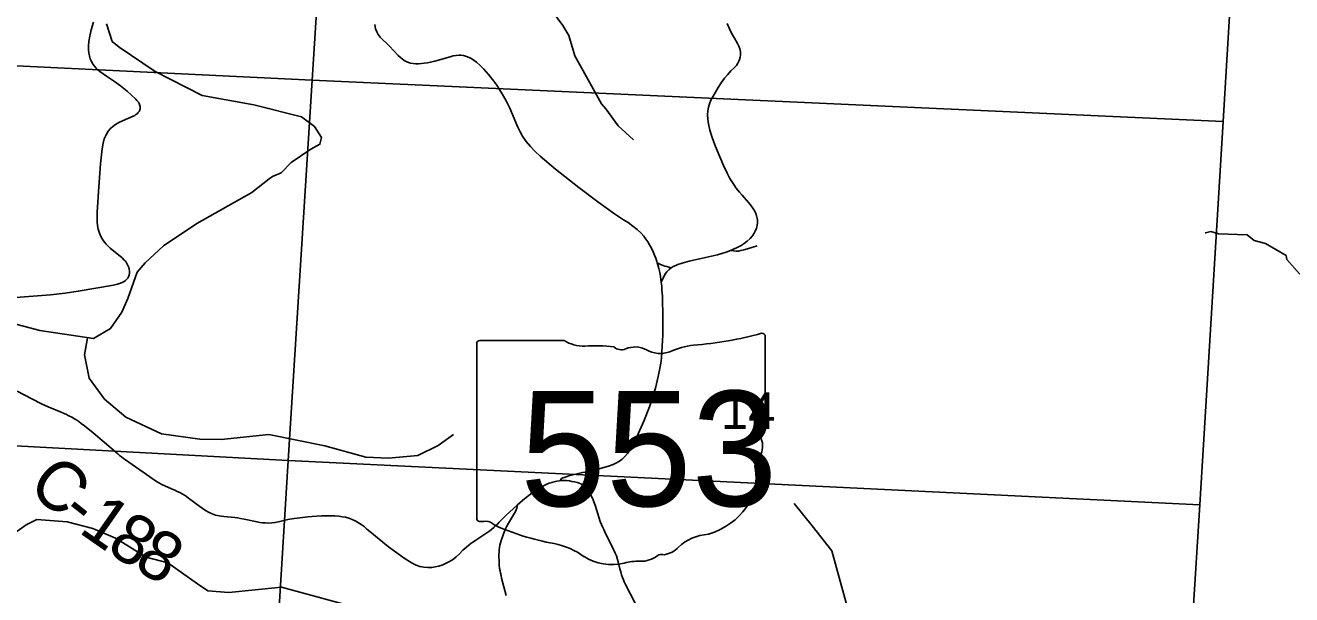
# Model space of a CAD drawing. Extents: x 396.2 to 468.4, y 232.6 to 279.1.
# Drawn here: x 417.748 to 419.195, y 265.475 to 266.126 of the extents above; entities that cross this region are included whole.
import ezdxf

# ---------------------------------------------------------------- set-up
doc = ezdxf.new("R2010")
doc.units = 0
for name, color, linetype in [('GM_X_County_Road', 7, 'Continuous'), ('GM_X_County_Road_Text', 7, 'Continuous'), ('GM_X_Minor_River', 7, 'Continuous'), ('GM_X_Section', 7, 'Continuous'), ('GM_X_Section_Text', 7, 'Continuous'), ('GM_X_State_Route', 7, 'Continuous'), ('GM_X_State_Shield', 7, 'Continuous'), ('GM_X_Township_Road', 7, 'Continuous')]:
    doc.layers.add(name, color=color, linetype=linetype)

msp = doc.modelspace()

# ---------------------------------------------------------------- linework, layer by layer
at = {"layer": 'GM_X_County_Road'}
for points in [[(418.4747, 265.8321), (418.4769, 265.8366), (418.4785, 265.8399), (418.4797, 265.8418), (418.4811, 265.8437), (418.4822, 265.845), (418.4837, 265.8466), (418.486, 265.8486), (418.4884, 265.8499), (418.4914, 265.8513), (418.4935, 265.8521), (418.4987, 265.8539), (418.5065, 265.8559), (418.5252, 265.8601), (418.5391, 265.8635), (418.5489, 265.8665), (418.554, 265.8684), (418.5573, 265.8697), (418.5615, 265.8716), (418.5659, 265.874), (418.5695, 265.8764), (418.573, 265.8791), (418.5762, 265.8821), (418.5788, 265.8849), (418.5809, 265.8881), (418.5821, 265.8903), (418.5835, 265.8939), (418.5843, 265.8969), (418.5846, 265.9001), (418.5845, 265.9032), (418.584, 265.9064), (418.5831, 265.9094), (418.5819, 265.9124), (418.5801, 265.9157), (418.5768, 265.9203), (418.5745, 265.9232), (418.5671, 265.9316), (418.5642, 265.9348), (418.5601, 265.9401), (418.5583, 265.9426), (418.5567, 265.9449), (418.5531, 265.9506), (418.55, 265.9566), (418.5458, 265.9655), (418.5426, 265.9728), (418.5404, 265.978), (418.536, 265.9889), (418.5328, 265.9976), (418.5303, 266.0059), (418.5286, 266.0131), (418.5278, 266.0186), (418.5276, 266.0235), (418.5278, 266.0278), (418.5286, 266.032), (418.5297, 266.0361), (418.5313, 266.04), (418.5339, 266.0448), (418.5367, 266.0495), (418.5399, 266.0548), (418.5432, 266.06), (418.5471, 266.0655), (418.5506, 266.0697), (418.5543, 266.0736), (418.5577, 266.0768), (418.5605, 266.0799), (418.5623, 266.0826), (418.5634, 266.0847), (418.564, 266.0866), (418.5647, 266.0893), (418.5651, 266.0916), (418.5651, 266.0953), (418.5644, 266.0989), (418.5634, 266.1018), (418.5618, 266.1051), (418.5584, 266.1109), (418.5551, 266.1167), (418.5527, 266.1216), (418.5502, 266.1279)], [(418.4701, 265.8541), (418.4732, 265.8526), (418.4756, 265.8515), (418.477, 265.851), (418.4787, 265.8504), (418.481, 265.8498), (418.4833, 265.8493), (418.486, 265.8486)], [(417.7383, 265.7073), (417.7552, 265.6985), (417.7663, 265.693), (417.7739, 265.6894), (417.7886, 265.6834), (417.792, 265.682), (417.7946, 265.6808), (417.7974, 265.6794), (417.8007, 265.6777), (417.8039, 265.6759), (417.8065, 265.6744), (417.8089, 265.6727), (417.8117, 265.6706), (417.8152, 265.6677), (417.8253, 265.6597), (417.8356, 265.6511), (417.8534, 265.6358), (417.8555, 265.634), (417.8577, 265.6323), (417.86, 265.6305), (417.8621, 265.6289), (417.8899, 265.6095), (417.8955, 265.6056), (417.9005, 265.6025), (417.9046, 265.6003), (417.9107, 265.5975), (417.9148, 265.5958), (417.9186, 265.5941), (417.9214, 265.5928), (417.9242, 265.5914), (417.927, 265.5899), (417.9296, 265.5885), (417.9319, 265.5869), (417.9343, 265.5852), (417.9472, 265.5755), (417.95, 265.5735), (417.9538, 265.571), (417.9577, 265.5688), (417.9612, 265.5672), (417.9652, 265.5658), (417.9693, 265.5649), (417.9748, 265.564), (417.9873, 265.5628), (417.9902, 265.5625), (417.9935, 265.5619), (417.9977, 265.5611), (418.0127, 265.5579), (418.0156, 265.5573), (418.0189, 265.5569), (418.0222, 265.5567), (418.0261, 265.5566), (418.0294, 265.5568), (418.0331, 265.5572), (418.037, 265.5579), (418.0479, 265.5605), (418.0502, 265.561), (418.0526, 265.5614), (418.0552, 265.5618), (418.0585, 265.5623), (418.0706, 265.5636), (418.0757, 265.5641), (418.0809, 265.5645), (418.0864, 265.5647), (418.0913, 265.5648), (418.097, 265.5648), (418.1016, 265.5647), (418.1059, 265.5644), (418.1098, 265.5639), (418.1136, 265.5632), (418.1174, 265.5621), (418.1212, 265.5606), (418.1248, 265.559), (418.1286, 265.5569), (418.1318, 265.5548), (418.1349, 265.5526), (418.1382, 265.5497), (418.1415, 265.5469), (418.1627, 265.5294), (418.1764, 265.5194), (418.1819, 265.5157), (418.1868, 265.5127), (418.1908, 265.5104), (418.1945, 265.5086), (418.1988, 265.5071), (418.2034, 265.5061), (418.208, 265.5057), (418.2124, 265.5058), (418.2162, 265.5064), (418.2203, 265.5075), (418.2248, 265.509), (418.2289, 265.5108), (418.2332, 265.5131), (418.237, 265.5155), (418.2404, 265.5181), (418.2441, 265.5216), (418.248, 265.5255), (418.2521, 265.5292), (418.2548, 265.5313), (418.2575, 265.5335), (418.2599, 265.5351), (418.2627, 265.5369), (418.2763, 265.5461), (418.2787, 265.5479), (418.281, 265.5498), (418.2831, 265.5516), (418.2852, 265.5535), (418.2873, 265.5555), (418.2895, 265.5576), (418.2971, 265.5653), (418.3099, 265.5771), (418.3161, 265.5823), (418.3204, 265.5859), (418.3253, 265.5896), (418.3307, 265.5935), (418.3352, 265.5964), (418.339, 265.5985), (418.3415, 265.5998), (418.344, 265.6009), (418.3467, 265.6021), (418.3495, 265.6031), (418.3522, 265.6039), (418.3552, 265.6045), (418.3584, 265.605), (418.3607, 265.6052), (418.3633, 265.6052), (418.3665, 265.6051), (418.3696, 265.6048), (418.3726, 265.6042), (418.3755, 265.6036), (418.3789, 265.6028), (418.3828, 265.6015), (418.3862, 265.6001), (418.3893, 265.5988)], [(418.3584, 265.605), (418.3597, 265.6064), (418.3608, 265.6074), (418.3622, 265.6082), (418.3635, 265.6088), (418.3661, 265.6096), (418.369, 265.6105), (418.3847, 265.6143), (418.3873, 265.6147), (418.39, 265.615), (418.393, 265.6149)]]:
    msp.add_lwpolyline(points, dxfattribs=at)
at = {"layer": 'GM_X_Minor_River'}
for points in [[(417.9351, 266.2922), (417.9971, 266.3168), (418.0171, 266.3173), (418.0325, 266.3137), (418.0797, 266.2872), (418.119, 266.2734), (418.1472, 266.2573), (418.1748, 266.2435), (418.2425, 266.2198), (418.2643, 266.2062), (418.3454, 266.1481), (418.3621, 266.1256), (418.3689, 266.114), (418.3758, 266.091), (418.4062, 266.0361), (418.4113, 266.0302), (418.4255, 266.0108), (418.4428, 265.9947)], [(417.7021, 265.793), (417.7641, 265.7768), (417.8258, 265.7675), (417.845, 265.7789), (417.8582, 265.7976), (417.865, 265.8132), (417.8756, 265.8433), (417.8847, 265.8543), (417.9058, 265.8737), (417.9436, 265.8993), (418.0067, 265.9344), (418.0263, 265.9501), (418.0301, 265.9527), (418.0403, 265.9569), (418.0516, 265.9687), (418.0739, 265.984), (418.0845, 265.9897), (418.0864, 265.9973), (418.0784, 266.0099), (418.0633, 266.0212), (418.0089, 266.0348), (417.9499, 266.0456), (417.8962, 266.0729), (417.8549, 266.1009), (417.847, 266.1073), (417.8406, 266.1274)], [(419.2047, 265.8412), (419.1899, 265.8579), (419.1892, 265.8624), (419.1654, 265.8764), (419.1525, 265.8798), (419.1446, 265.8863), (419.1117, 265.8873), (419.103, 265.89), (419.0969, 265.8884), (419.0965, 265.8884)], [(417.8188, 265.7685), (417.8155, 265.7489), (417.8205, 265.7223), (417.8383, 265.6984), (417.8627, 265.6775), (417.9033, 265.6586), (417.9473, 265.6526), (417.9716, 265.6523), (418.0262, 265.6577), (418.0899, 265.645), (418.137, 265.6321), (418.1628, 265.6307), (418.1965, 265.6338), (418.2196, 265.6452), (418.2371, 265.6578)], [(417.5791, 265.581), (417.5819, 265.5599), (417.6126, 265.5538), (417.6771, 265.5536), (417.7249, 265.5431), (417.7378, 265.5469), (417.7488, 265.5545), (417.7609, 265.5606), (417.7954, 265.5581), (417.8247, 265.5505), (417.8509, 265.5392), (417.8858, 265.5176), (417.9105, 265.5112), (417.9447, 265.487), (417.9564, 265.479), (417.9803, 265.4772), (418.0406, 265.4834), (418.1203, 265.4615), (418.1438, 265.4578), (418.1552, 265.4502), (418.1598, 265.4468)], [(418.6972, 265.2282), (418.705, 265.3439), (418.7021, 265.3975), (418.6877, 265.4595), (418.6697, 265.525), (418.6471, 265.5534), (418.6267, 265.5791)]]:
    msp.add_lwpolyline(points, dxfattribs=at)
at = {"layer": 'GM_X_Section'}
for points in [[(417.1188, 266.2992), (418.0878, 266.2553), (418.0756, 266.0632), (417.0456, 266.113), (417.0573, 266.3036)], [(419.0595, 266.2102), (419.1285, 266.207), (419.1169, 266.0156), (418.0756, 266.0632), (418.0878, 266.2553)], [(417.0456, 266.113), (418.0756, 266.0632), (418.0481, 265.6281), (417.0199, 265.6834)], [(418.0756, 266.0632), (419.1169, 266.0156), (419.0905, 265.5773), (418.0481, 265.6281)], [(418.0481, 265.6281), (418.0224, 265.2055), (416.997, 265.2568), (417.0199, 265.6834)], [(419.0905, 265.5773), (419.0623, 265.1301), (418.2588, 265.19), (418.0224, 265.2055), (418.0481, 265.6281)]]:
    msp.add_lwpolyline(points, close=True, dxfattribs=at)
msp.add_lwpolyline([(419.8058, 265.0737), (419.0623, 265.1301), (419.0905, 265.5773), (419.1169, 266.0156), (419.1285, 266.207), (419.6185, 266.1841)], dxfattribs=at)
at = {"layer": 'GM_X_State_Route'}
for points in [[(417.7019, 265.8117), (417.7765, 265.8175), (417.7932, 265.8194), (417.8081, 265.8217), (417.8486, 265.8288), (417.853, 265.8298), (417.8565, 265.8309), (417.8592, 265.832), (417.8607, 265.8329), (417.8621, 265.8338), (417.8635, 265.8351), (417.8648, 265.8366), (417.8658, 265.8383), (417.8664, 265.8402), (417.8668, 265.8427), (417.8668, 265.8448), (417.8665, 265.8468), (417.8659, 265.849), (417.865, 265.8512), (417.8639, 265.8533), (417.8624, 265.8555), (417.8606, 265.8574), (417.8583, 265.8597), (417.8445, 265.8711), (417.842, 265.8736), (417.84, 265.8756), (417.8381, 265.8779), (417.8362, 265.8804), (417.8341, 265.8842), (417.8325, 265.888), (417.8311, 265.8925), (417.8302, 265.8969), (417.8299, 265.901), (417.8298, 265.9054), (417.8299, 265.9121), (417.8319, 265.9409), (417.8337, 265.9674), (417.8346, 265.9778), (417.8355, 265.9846), (417.8367, 265.9909), (417.838, 265.9958), (417.8401, 266.0005), (417.8425, 266.0047), (417.845, 266.0078), (417.8476, 266.0101), (417.8509, 266.0124), (417.8545, 266.0145), (417.8586, 266.0164), (417.8711, 266.0218), (417.8727, 266.0226), (417.8741, 266.0236), (417.8755, 266.0247), (417.8764, 266.0255), (417.8772, 266.0264), (417.8778, 266.0273), (417.8781, 266.0281), (417.8785, 266.029), (417.8788, 266.0302), (417.8789, 266.0316), (417.8788, 266.0329), (417.8787, 266.0342), (417.8783, 266.0354), (417.8778, 266.0365), (417.877, 266.0377), (417.8762, 266.0388), (417.8753, 266.0399), (417.8742, 266.0412), (417.8642, 266.0504), (417.8564, 266.0566), (417.8498, 266.0614), (417.8405, 266.0676), (417.833, 266.0729), (417.8304, 266.075), (417.8285, 266.0768), (417.8267, 266.0789), (417.8252, 266.0811), (417.8233, 266.0845), (417.822, 266.0875), (417.8209, 266.0909), (417.8203, 266.0938), (417.8199, 266.0981), (417.8199, 266.1023), (417.8203, 266.1072), (417.8213, 266.1133), (417.8229, 266.1205), (417.8255, 266.1294)], [(418.4451, 265.4644), (418.4338, 265.4865), (418.4324, 265.4895), (418.4314, 265.4918), (418.4304, 265.4945), (418.4294, 265.4975), (418.4283, 265.501), (418.4274, 265.5044), (418.4253, 265.5122), (418.4247, 265.5149), (418.4234, 265.519), (418.4221, 265.522), (418.4201, 265.5265), (418.4101, 265.5465), (418.4089, 265.5492), (418.4075, 265.5522), (418.4063, 265.5551), (418.405, 265.5585), (418.4007, 265.572), (418.3991, 265.577), (418.3977, 265.5808), (418.3968, 265.5833), (418.3959, 265.5852), (418.395, 265.5871), (418.3893, 265.5988), (418.3888, 265.5996), (418.3884, 265.6008), (418.388, 265.6019), (418.3877, 265.6029), (418.3876, 265.604), (418.3875, 265.605), (418.3876, 265.606), (418.3877, 265.6069), (418.3879, 265.6079), (418.3882, 265.6088), (418.3886, 265.6097), (418.3891, 265.6106), (418.3897, 265.6116), (418.3904, 265.6126), (418.3913, 265.6134), (418.3922, 265.6143), (418.393, 265.6149), (418.3943, 265.6156), (418.3954, 265.6162), (418.3964, 265.6166), (418.3972, 265.6169), (418.3983, 265.6173), (418.3994, 265.6176), (418.4142, 265.6216), (418.4196, 265.6234), (418.4236, 265.6253), (418.4269, 265.6273), (418.4299, 265.6296), (418.4331, 265.6327), (418.4359, 265.6361), (418.4392, 265.6407), (418.4424, 265.6461), (418.4469, 265.6551), (418.4549, 265.6733), (418.4612, 265.6896), (418.4679, 265.7109), (418.4713, 265.7242), (418.4728, 265.7314), (418.4741, 265.7396), (418.4748, 265.7457), (418.4753, 265.752), (418.4758, 265.7589), (418.4761, 265.7652), (418.4763, 265.7713), (418.4764, 265.7909), (418.4759, 265.8161), (418.4755, 265.823), (418.4752, 265.8274), (418.4747, 265.8321), (418.4743, 265.835), (418.4737, 265.8388), (418.4729, 265.8432), (418.4719, 265.8477), (418.4708, 265.8518), (418.4701, 265.8541), (418.4697, 265.8557), (418.4684, 265.8595), (418.4671, 265.8629), (418.4653, 265.8668), (418.4635, 265.8708), (418.4613, 265.8749), (418.4594, 265.8782), (418.4572, 265.8814), (418.4548, 265.8846), (418.4518, 265.8879), (418.4472, 265.8921), (418.4423, 265.8961), (418.4367, 265.9001), (418.4315, 265.9034), (418.4212, 265.9103), (418.4022, 265.9241), (418.3805, 265.9403), (418.3539, 265.9612), (418.3361, 265.9763), (418.3304, 265.9816), (418.3252, 265.987), (418.3203, 265.993), (418.316, 265.9989), (418.3132, 266.0039), (418.3107, 266.0093), (418.3083, 266.0148), (418.3016, 266.0309), (418.2994, 266.0355), (418.2974, 266.0395), (418.2945, 266.0447), (418.2916, 266.0494), (418.2891, 266.0534), (418.2866, 266.0572), (418.2833, 266.0619), (418.2804, 266.0657), (418.2772, 266.0696), (418.2718, 266.0755), (418.2675, 266.0798), (418.2634, 266.0835), (418.2607, 266.0857), (418.2581, 266.0874), (418.2552, 266.0889), (418.252, 266.0902), (418.2487, 266.0911), (418.2456, 266.0915), (418.2431, 266.0916), (418.2402, 266.0913), (418.2367, 266.0907), (418.2332, 266.0899), (418.216, 266.0849), (418.211, 266.0836), (418.2073, 266.0829), (418.2038, 266.0824), (418.2006, 266.082), (418.1972, 266.0818), (418.194, 266.0818), (418.191, 266.0821), (418.1881, 266.0826), (418.1856, 266.0834), (418.183, 266.0845), (418.1806, 266.0857), (418.1784, 266.0873), (418.1765, 266.089), (418.1741, 266.0913), (418.1639, 266.102), (418.1534, 266.1123), (418.1511, 266.1152), (418.1494, 266.1183), (418.148, 266.1218), (418.1473, 266.1266)]]:
    msp.add_lwpolyline(points, dxfattribs=at)
at = {"layer": 'GM_X_State_Shield'}
for p, q in [((418.2639, 265.7619), (418.2639, 265.5617)), ((418.3636, 265.7653), (418.2671, 265.7653)), ((418.5935, 265.6656), (418.5935, 265.7703)), ((418.5934, 265.6656), (418.5935, 265.6656))]:
    msp.add_line(p, q, dxfattribs=at)
for centre, major_axis, start_param, end_param in [((418.4761, 266.0381), (0.3495, 0), 4.814394, 5.042369), ((418.5898, 265.7707), (0.00367, 0), 6.141152, 7.989035), ((418.2677, 265.7623), (0.00382, 0), 1.712693, 3.28349), ((418.3866, 265.7885), (0.037, 0), 4.042523, 4.731795), ((418.3989, 265.653), (0.133, 0), 1.404758, 1.657858), ((418.4291, 265.7633), (0.0107, 0), 3.836095, 5.185415), ((418.4448, 265.7402), (0.0222, 0), 0.950623, 2.079405), ((418.5206, 265.7042), (0.0703, 0), 1.699011, 2.107814), ((418.4734, 265.7719), (0.0267, 0), 4.081561, 5.145723), ((418.5926, 265.6579), (0.00568, 0), 1.883978, 3.671073), ((418.5895, 265.6652), (0.00393, 0), 5.05454, 6.418171), ((418.5565, 265.6447), (0.0341, 0), 5.934695, 6.695948), ((418.6066, 265.6218), (0.0248, 0), 2.387724, 3.262537), ((418.4956, 265.6085), (0.0874, 0), 5.101752, 6.440018), ((418.2677, 265.5613), (0.00385, 0), 3.00124, 4.508301), ((418.2683, 265.5818), (0.0294, 0), 4.665946, 4.897461), ((418.2743, 265.5502), (0.0106, 0), 0.519207, 1.627899), ((418.4081, 265.73), (0.2524, 0), 4.195997, 4.488961), ((418.5325, 265.5056), (0.0479, 0), 1.647645, 2.488434), ((418.3329, 265.4718), (0.079, 0), 0.823519, 1.323587), ((418.4718, 265.5424), (0.0282, 0), 4.937069, 5.64225), ((418.4183, 265.5492), (0.0501, 0), 4.026481, 4.996735), ((418.4472, 265.48), (0.0412, 0), 1.495662, 1.94098), ((418.4509, 265.5342), (0.0267, 0), 4.691044, 5.507374), ((418.475, 265.5148), (0.00752, 0), 1.147584, 2.315152)]:
    msp.add_ellipse(centre, major_axis=major_axis, ratio=0.8, start_param=start_param, end_param=end_param, dxfattribs=at)
at = {"layer": 'GM_X_Township_Road'}
for points in [[(418.554, 265.8684), (418.5573, 265.8678), (418.5602, 265.8675), (418.5628, 265.8676), (418.5656, 265.8681), (418.5689, 265.8689), (418.5732, 265.8701), (418.5792, 265.872), (418.5842, 265.8737)], [(418.2975, 265.4736), (418.2922, 265.4937), (418.2916, 265.4965), (418.2909, 265.4992), (418.2904, 265.5019), (418.2899, 265.5048), (418.2895, 265.5086), (418.2892, 265.5129), (418.289, 265.5179), (418.289, 265.5207), (418.2892, 265.5235), (418.2895, 265.5262), (418.2898, 265.5285), (418.2903, 265.5312), (418.291, 265.534), (418.2917, 265.5367), (418.2928, 265.5399), (418.2938, 265.5431), (418.2952, 265.5463), (418.2964, 265.5492), (418.2979, 265.5522), (418.3001, 265.5563), (418.3079, 265.5698), (418.3089, 265.5718), (418.3096, 265.5737), (418.31, 265.5755), (418.3099, 265.5771)]]:
    msp.add_lwpolyline(points, dxfattribs=at)

# ---------------------------------------------------------------- texts
at = {"layer": 'GM_X_County_Road_Text'}
for s, rotation, p in [('C', 318.857, (417.7485, 265.5962)), ('-', 321.3811, (417.7857, 265.5637)), ('1', 325.1055, (417.8072, 265.5468)), ('8', 328.1275, (417.8386, 265.5249)), ('8', 329.4883, (417.8696, 265.5057))]:
    msp.add_text(s, height=0.0568, rotation=rotation, dxfattribs=at).set_placement(p)
at = {"layer": 'GM_X_Section_Text'}
msp.add_text('14', height=0.04186, rotation=0, dxfattribs=at).set_placement((418.5429, 265.6643))
at = {"layer": 'GM_X_State_Shield'}
msp.add_text('553', height=0.13184, dxfattribs=at).set_placement((418.3133, 265.5759))

doc.saveas('drawing.dxf')
